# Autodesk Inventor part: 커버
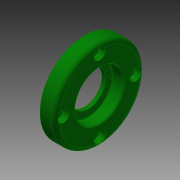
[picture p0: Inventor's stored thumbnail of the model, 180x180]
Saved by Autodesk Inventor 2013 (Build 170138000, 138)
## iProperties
Created: 2018-11
Part Number: 커버
Material: 알루미늄 6061
Document SubType Name: Modeling
Designer: mduedu
Density: 1 g/cm^3
Author: mduedu
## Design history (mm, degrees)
revolve "회전1" stored, may be unused: angle "d7" = 90 deg
revolve "회전2" stored, may be unused: angle "d14" = 90 deg
fillet "모깎기1" dims "d15" = 0.3
chamfer "모따기1" distance "d16" = 0.8; stored, may be unused: second distance "d17" = 2, angle "d18" = 30 deg
fillet "모깎기2" dims "d19" = 1, "d35" = 3
chamfer "모따기2" distance "d20" = 0.5; stored, may be unused: second distance "d21" = 2, angle "d22" = 30 deg
sketch "스케치5" dims "d55" = 60
  geometry: 3 further points
  constraints: 2 vertical alignment, 1 coincident, 2 other
hole "구멍3" sketch "스케치5" at (0, 30) diameter "d56" = 4.5; stored, may be unused: countersink angle "d60" = 90 deg, drill point angle "d62" = 118 deg; dims "d57" = 6, "d58" = 8, "d59" = 4.4, "d61" = 8
node "솔리드1"
pattern_circular "원형 패턴1" dims angle "d64" = 360 deg
sketch "스케치1"
  geometry: L1 (0, 0)-(3, 0); L2 (3, 23.5)-(0, 23.5); L3 (0, 23.5)-(0, 0); L4 (3, 0)-(9, 0); L5 (11, 38)-(3, 38); L6 (3, 38)-(3, 23.5); L7 (9, 0)-(14, 0); L8 (14, 0)-(14, 35); A1 r 3 centre (11, 35) between (14, 35) and (11, 38)
  constraints: 16 end point, 3 horizontal, 2 parallel, 2 point on circle, 2 tangent, 1 centre point, 1 perpendicular, 1 vertical
  dimensions: "d0" = 76 diameter of L5 L4; "d3" = 47 diameter of L2 L1; "d6" = 14 distance between parallel lines of L8 L3; "d46" = 3 distance between parallel lines of L6 L3; "d47" = 3 radius of A1
sketch "스케치2"
  geometry: L1 (0, -23.5)-(0, 23.5) reference; L2 (0, 23.5)-(3, 23.5) reference; L3 (3, 23.5)-(3, 38) reference; L4 (3, 38)-(11, 38) reference; L5 (11, -38)-(3, -38) reference; L6 (3, -38)-(3, -23.5) reference; L7 (3, -23.5)-(0, -23.5) reference; L8 (0, 0)-(3, 0); L9 (3, 0)-(3, 20); L10 (3, 20)-(0, 20); L11 (0, 20)-(0, 0); L12 (3, 0)-(5.7, 0); L13 (5.7, 0)-(5.7, 12.5); L14 (5.7, 12.5)-(3, 12.5); L15 (3, 12.5)-(3, 0); L16 (5.7, 0)-(14, 0); L17 (14, 0)-(14, 17.5); L18 (14, 17.5)-(5.7, 17.5); L19 (5.7, 17.5)-(5.7, 0); L20 (14, 35)-(14, -35) reference; A1 r 3 centre (11, 35) between (14, 35) and (11, 38) reference; A2 r 3 centre (11, -35) between (11, -38) and (14, -35) reference
  constraints: 24 end point, 6 parallel, 3 horizontal, 3 perpendicular
  dimensions: "d8" = 35 diameter of L18 L16; "d10" = 25 diameter of L14 L12; "d11" = 40 diameter of L10 L8; "d12" = 3 distance of L9.end L10.end; "d13" = 8.3 distance of L17.end L18.end
node "절단 모서리 투영1"
